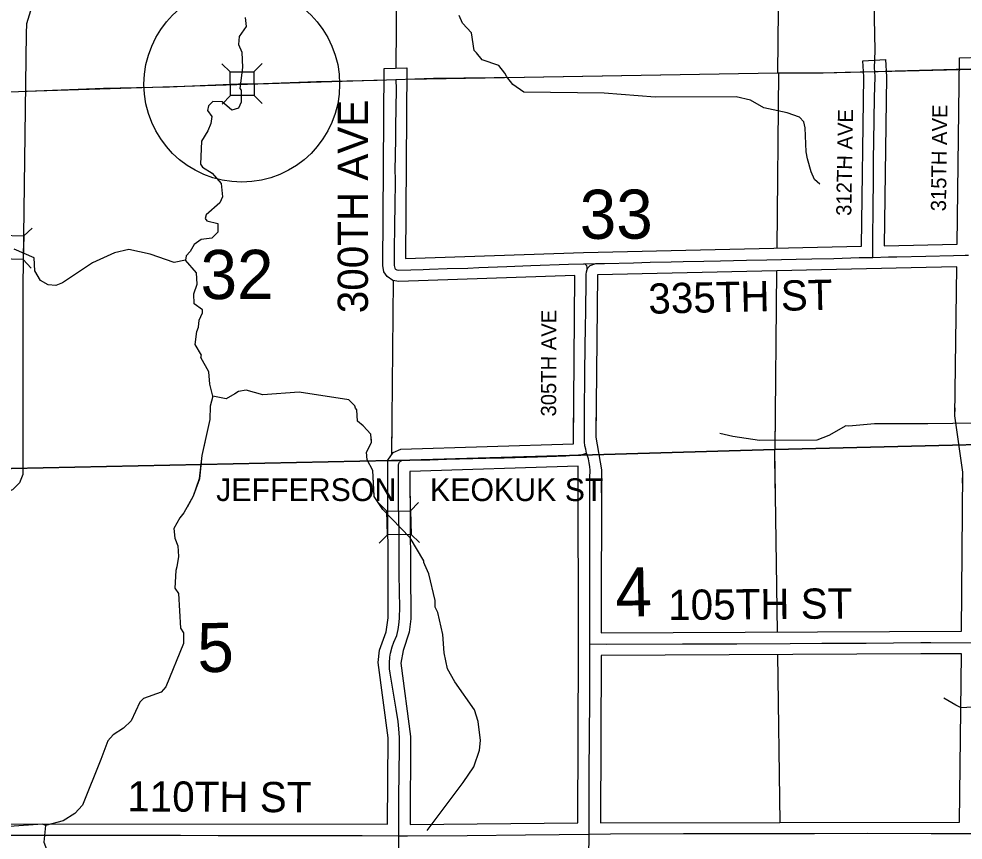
# Model space of a CAD drawing. Extents: x 10133 to 81668, y 7924 to 11018.
# Drawn here: x 11451.5 to 11826.5, y 8891.2 to 9217.2 of the extents above; entities that cross this region are included whole.
import ezdxf

# ---------------------------------------------------------------- set-up
doc = ezdxf.new("R2010")
doc.units = 0
for name, color, linetype in [('SheetBorder', 7, 'Continuous'), ('tdCoCityStreetMajor', 7, 'Continuous'), ('tdCoCityStreetMinor', 7, 'Continuous'), ('tdCoHydroRiver', 7, 'Continuous'), ('tdCoPriNonDiv', 7, 'Continuous'), ('tdCoRROwnerTxt', 7, 'Continuous'), ('tdCoShieldCoRte', 7, 'Continuous'), ('tdCoShieldCoRteHrd', 7, 'Continuous'), ('tdCoShieldStRte', 7, 'Continuous'), ('tdCoStrucNonDivPri', 7, 'Continuous'), ('tdCoStrucSec', 7, 'Continuous'), ('tdCoSurfGravel', 7, 'Continuous'), ('tdCoTwpBndryShd', 7, 'Continuous'), ('tdCoTwpNameTxt', 7, 'Continuous'), ('tdCoTwpRngTxt', 7, 'Continuous')]:
    doc.layers.add(name, color=color, linetype=linetype)

msp = doc.modelspace()

# ---------------------------------------------------------------- linework, layer by layer
at = {"layer": 'SheetBorder'}
msp.add_circle((11540.08, 9191.25), 38.85, dxfattribs=at)
at = {"layer": 'tdCoCityStreetMajor'}
for points in [[(11678.28, 8969.06), (11684.98, 8969.01), (11715.05, 8969.16), (11736.66, 8969.05), (11757.89, 8969.31), (11770.39, 8969.32)], [(11599.8, 8741.54), (11599.87, 8743), (11599.9, 8755.47), (11600.09, 8765.6), (11600.31, 8788.83), (11600.53, 8804.37), (11600.61, 8811.43), (11600.64, 8813.69), (11600.83, 8814.84), (11601.09, 8816.13), (11601.53, 8817.54), (11601.94, 8819.05), (11602.05, 8822.24), (11602.12, 8834.66), (11602.23, 8848.06), (11602.23, 8861.26), (11602.45, 8883.97), (11602.45, 8892.95)]]:
    msp.add_lwpolyline(points, dxfattribs=at)
at = {"layer": 'tdCoCityStreetMinor'}
for points in [[(11790.62, 9122.52), (11790.65, 9123.5), (11790.67, 9124.51), (11790.7, 9129.91), (11790.8, 9142.04), (11790.87, 9153.63), (11790.99, 9161.65), (11791.04, 9168.45), (11791.29, 9185.96), (11791.58, 9194.19), (11791.46, 9196.37)], [(11601.22, 9193.13), (11601.32, 9189.36), (11601.06, 9174.4), (11601.06, 9170.65), (11600.96, 9161.99), (11600.87, 9158.17), (11600.94, 9152.7), (11600.87, 9143.18), (11600.69, 9135.53), (11600.64, 9125), (11600.62, 9119.26), (11600.79, 9118.29), (11601.03, 9117.97), (11601.14, 9117.83), (11601.61, 9117.6), (11602.3, 9117.48), (11612.14, 9117.75), (11614.58, 9117.83), (11621.56, 9118.05), (11629.89, 9118.27), (11634.18, 9118.47), (11645.28, 9118.89), (11654.8, 9119.26), (11669.87, 9119.82), (11675.93, 9120)], [(11790.62, 9122.52), (11796.94, 9122.68), (11800.2, 9122.78), (11811.71, 9123.03), (11822.69, 9123.25), (11827.28, 9123.35), (11828.65, 9123.44)], [(11675.93, 9120), (11680.65, 9120.05)], [(11677.27, 9117.7), (11677.22, 9118.67), (11677.09, 9119.11), (11676.9, 9119.33), (11676.6, 9119.63), (11675.93, 9120)], [(11677.27, 9117.7), (11677.66, 9118.49), (11678.48, 9119.28), (11680.65, 9120.05)], [(11680.65, 9120.05), (11684.15, 9120.09), (11695.56, 9120.34), (11702.25, 9120.59), (11710.53, 9120.74), (11715.34, 9120.83), (11723.58, 9121.01), (11730.19, 9121.13), (11740.49, 9121.38), (11748.51, 9121.55), (11760.17, 9121.82), (11766.39, 9121.94), (11775.22, 9122.14), (11785.3, 9122.41), (11790.16, 9122.51), (11790.62, 9122.52)], [(11677.02, 9044.74), (11676.63, 9046.36), (11676.33, 9047.74), (11676.23, 9049.27), (11676.11, 9051.05), (11676.13, 9054.92), (11676.23, 9062.05), (11676.36, 9075.26), (11676.45, 9088.56), (11676.6, 9093.19), (11676.7, 9102.76), (11676.8, 9111.86), (11676.82, 9115.68), (11677, 9116.79), (11677.27, 9117.7)], [(11677.02, 9044.74), (11676.63, 9046.36), (11676.33, 9047.74), (11676.23, 9049.27), (11676.11, 9051.05), (11676.13, 9054.92), (11676.19, 9058.89)], [(11602.45, 8892.95), (11602.45, 8894.37), (11602.42, 8908.28), (11602.64, 8927.62), (11602.64, 8931.99), (11602.42, 8935.32), (11602.27, 8936.82), (11602.12, 8938.31), (11601.38, 8943.2), (11600.27, 8949.48), (11598.98, 8957.47), (11598.79, 8959.25), (11598.72, 8961.58), (11598.87, 8963.84), (11599.16, 8965.43), (11599.79, 8967.87), (11600.49, 8969.72), (11601.64, 8972.46), (11602.23, 8974.79), (11602.49, 8976.67), (11602.68, 8979.19), (11602.7, 8979.72), (11602.86, 8983.41), (11602.6, 8996.61), (11602.57, 9013.37), (11602.34, 9024.58), (11602.3, 9035.07), (11602.3, 9035.54), (11602.3, 9040.07), (11602.37, 9040.69), (11602.67, 9041.28), (11603.23, 9041.79), (11603.24, 9041.8), (11603.68, 9041.96), (11603.73, 9041.97), (11614.75, 9042.22), (11621.31, 9042.42), (11636.97, 9042.84), (11644.32, 9043.01), (11657.49, 9043.4), (11665.09, 9043.58), (11668.73, 9043.72), (11671.74, 9043.99), (11673.81, 9044.12), (11675.17, 9044.27), (11676.21, 9044.51), (11677.02, 9044.74)], [(11602.33, 9026.92), (11602.3, 9035.07), (11602.3, 9035.53), (11602.3, 9040.07), (11602.37, 9040.69), (11602.67, 9041.28), (11603.23, 9041.79), (11603.24, 9041.8), (11603.68, 9041.95), (11603.73, 9041.97), (11614.75, 9042.22), (11621.31, 9042.42), (11636.97, 9042.83), (11644.32, 9043.01), (11657.49, 9043.4), (11665.09, 9043.57), (11668.73, 9043.72), (11671.74, 9043.99), (11673.81, 9044.12), (11675.17, 9044.26), (11676.21, 9044.51), (11677.02, 9044.74)], [(11677.96, 8893.57), (11677.96, 8903.69), (11678.03, 8919.82), (11678.11, 8930.69), (11678.22, 8948.93), (11678.22, 8955.96), (11678.29, 8966.72), (11678.28, 8969.06), (11678.25, 8978.93), (11678.29, 8995.02), (11678.22, 9006.12), (11678.25, 9022.1), (11678.3, 9035.09), (11678.35, 9037.98), (11678.23, 9039.53), (11678.03, 9041.01), (11677.69, 9042.59), (11677.17, 9044.14), (11677.02, 9044.74)], [(11678.28, 9028.95), (11678.3, 9035.09), (11678.35, 9037.98), (11678.23, 9039.53), (11678.03, 9041.01), (11677.69, 9042.59), (11677.17, 9044.14), (11677.02, 9044.74)], [(11770.39, 8969.32), (11788, 8969.34), (11809.75, 8969.68), (11813.71, 8969.68), (11830.35, 8969.55)], [(11412.41, 8893.16), (11421.42, 8893.13), (11452.49, 8893.17), (11490, 8893.17), (11515.67, 8893.17), (11530.73, 8893.06), (11548, 8892.98), (11571.01, 8893.06), (11587.84, 8892.98), (11602.45, 8892.95)], [(11602.45, 8892.95), (11605.82, 8892.95), (11629.57, 8893.09), (11652.69, 8893.35), (11666.15, 8893.46), (11677.96, 8893.57)], [(11676.69, 8741.59), (11676.66, 8745.59), (11676.7, 8757.06), (11677.03, 8775.48), (11677.14, 8786.1), (11677.37, 8801.23), (11677.4, 8811.81), (11677.59, 8828.64), (11677.62, 8839.96), (11677.74, 8852.24), (11677.74, 8863.63), (11677.81, 8879.02), (11677.96, 8892.33), (11677.96, 8893.57)], [(11677.96, 8893.57), (11686.46, 8893.65), (11715.42, 8893.76), (11735.36, 8893.83), (11751.89, 8893.83), (11767.47, 8893.83), (11788.41, 8893.95), (11813.85, 8893.83), (11829.54, 8893.79)]]:
    msp.add_lwpolyline(points, dxfattribs=at)
at = {"layer": 'tdCoHydroRiver'}
for points in [[(11541.44, 9217.78), (11541.74, 9214.24), (11538.97, 9210.16), (11538.78, 9207.08), (11540.02, 9204.03), (11540.36, 9197.87), (11539.31, 9189.57), (11539.8, 9188.87), (11539.88, 9184.13), (11538.73, 9181.75), (11536.14, 9180.99), (11532.3, 9184.24), (11528.51, 9184.42), (11526.88, 9182.73), (11526.43, 9180.83), (11528.13, 9178.49), (11527.71, 9175.64), (11526.57, 9172.78), (11524.03, 9168.71), (11523.72, 9159.47), (11524.45, 9158.3), (11528.27, 9156), (11531.89, 9151.79), (11532.46, 9146.59), (11531.31, 9144.21), (11525.95, 9139.38), (11525.5, 9137.95), (11526.22, 9137.02), (11530.5, 9135.91), (11530.56, 9132.59), (11528.23, 9130.18), (11523.98, 9129.64), (11521.17, 9127.7), (11519.56, 9124.83), (11517.93, 9123.14), (11517.72, 9121.48)], [(11769.64, 9151.53), (11767.48, 9153.38), (11766.24, 9156.44), (11764.73, 9161.62), (11764.21, 9164.46), (11763.82, 9173.92), (11763.3, 9176.28), (11761.61, 9178.15), (11756.61, 9179.96), (11747.34, 9181.93), (11742.08, 9184.92), (11736.38, 9186.25), (11704.17, 9186.18), (11684.02, 9187.74), (11652.05, 9188.15), (11647.74, 9191.15), (11645.32, 9194.19), (11644.58, 9195.6), (11642.16, 9198.64), (11635.5, 9200.89), (11633.32, 9203.7), (11632.35, 9204.63), (11631.29, 9211.71), (11627.67, 9215.44), (11626.44, 9218.5)], [(11517.72, 9121.48), (11513.24, 9120.46), (11503.71, 9123.85), (11495.16, 9125.6), (11489.5, 9124.32), (11480.8, 9120.39), (11468.86, 9112.37), (11466.27, 9111.38), (11463.19, 9111.57), (11460.08, 9113.41), (11457.89, 9117.16), (11457.56, 9122.37), (11449.69, 9125.79)], [(11528.58, 9067.44), (11527.31, 9072.15), (11526.99, 9077.12), (11523.82, 9082.75), (11524.04, 9083.7), (11521.6, 9087.92), (11522.22, 9093.14), (11522.91, 9094.81), (11523.1, 9097.66), (11524.47, 9100.52), (11524.45, 9101.71), (11521.1, 9104.02), (11521.03, 9108.04), (11522.38, 9111.85), (11522.07, 9116.35), (11517.72, 9121.48)], [(11528.58, 9067.44), (11527.46, 9063.4), (11527.31, 9058.18), (11524.24, 9043.92), (11523.21, 9034.67), (11520.72, 9027.76), (11518.34, 9023.43)], [(11592.69, 9027.83), (11592.06, 9037.96), (11589.86, 9042.18), (11589.57, 9045.26), (11591.63, 9049.08), (11591.34, 9052.39), (11588.21, 9055.65), (11586.05, 9057.51), (11585.73, 9062.01), (11585.25, 9062.71), (11585, 9063.65), (11582.59, 9065.98), (11562.89, 9068.96), (11548.46, 9068.01), (11541.8, 9069.79), (11538.73, 9069.27), (11537.32, 9068.3), (11533.8, 9066.34), (11528.58, 9067.44)], [(11893.46, 9035.42), (11889.44, 9038.85), (11883.23, 9041.58), (11870.17, 9043.47), (11865.88, 9045.05), (11863.45, 9048.8), (11858.37, 9053.35), (11852.86, 9056.01), (11842.4, 9056.88), (11812.5, 9056.44), (11791.37, 9056.49), (11781.18, 9055.46)], [(11781.18, 9055.46), (11779.99, 9055.66), (11773.15, 9051.85), (11768.43, 9050.01), (11745.6, 9049.87), (11735.11, 9051.37), (11729.86, 9052.59)], [(11525.37, 9049.2), (11524.23, 9043.92), (11523.2, 9034.67), (11520.71, 9027.76), (11517.04, 9021.07), (11515.41, 9019.15), (11513.12, 9014.85), (11513.42, 9011.06), (11514.65, 9008.01), (11514.96, 9003.75), (11514.32, 8999.71), (11513.87, 8998.28), (11513.51, 8991.17), (11514.97, 8989.07), (11515.67, 8975.35), (11516.89, 8973.47), (11516.96, 8969.21), (11509.91, 8952.04), (11508.05, 8949.88), (11500.99, 8947.39), (11499.59, 8945.95), (11496.16, 8938.55), (11493.13, 8935.66), (11488.92, 8932.98), (11486.83, 8930.58), (11484.11, 8923.19), (11476.83, 8905.07), (11473.81, 8901.71), (11469.13, 8898.79), (11462.05, 8897.01)], [(11613.63, 8895.06), (11628, 8914.01), (11632.15, 8920.23), (11634.41, 8926.9), (11634.82, 8930.7), (11633.98, 8938.26), (11632.48, 8942.97), (11624.72, 8953.97), (11621.79, 8959.13), (11620.5, 8965.5), (11619.9, 8972.83), (11617.86, 8981.56), (11616.88, 8983.68), (11616.84, 8986.28), (11614.29, 8996.89), (11612.81, 9000.42), (11612.32, 9001.36), (11612.31, 9002.07), (11606.95, 9011.21), (11596.1, 9022.4), (11592.7, 9027.55), (11592.05, 9037.96), (11589.85, 9042.18), (11589.56, 9045.26), (11591.63, 9049.08), (11591.52, 9050.32)], [(11898.87, 9027.66), (11897.46, 9027.16), (11894.21, 9023.55), (11891.25, 9017.33), (11889.04, 9008.53), (11883.39, 8993.51), (11875.66, 8975.85), (11874.99, 8973.94), (11870.42, 8964.86), (11866.03, 8958.62), (11859.76, 8952.11), (11850.62, 8946.97), (11841.19, 8944.67), (11825.81, 8943.68), (11823.66, 8944.82), (11818.87, 8947.58)], [(11462.05, 8897.01), (11461.45, 8890.37), (11462.45, 8887.55), (11465.59, 8884.05), (11466.09, 8882.16), (11465, 8876.7), (11465.07, 8872.44), (11465.12, 8869.6), (11466.35, 8866.77), (11467.11, 8863.71), (11467.36, 8862.77), (11467.97, 8854.96), (11467.54, 8852.11), (11465.98, 8846.17), (11465.55, 8844.03), (11463.98, 8838.79), (11461.46, 8833.54), (11461.34, 8826.91), (11462.07, 8825.26), (11462.04, 8813.19), (11461.62, 8810.1), (11460.71, 8807.72), (11454.75, 8796.01), (11436.23, 8771.08)], [(11462.05, 8897.01), (11460.86, 8897.47), (11447.85, 8896.54)]]:
    msp.add_lwpolyline(points, dxfattribs=at)
at = {"layer": 'tdCoPriNonDiv'}
for points in [[(11456.75, 9222.11), (11454.63, 9215.25), (11454.45, 9211.45), (11453.15, 9111.11), (11453.09, 9036.32), (11451.81, 9032.96), (11448.95, 9030.28), (11446.21, 9029.19), (11438.5, 9028.81), (11437.64, 9028.09), (11437.23, 9026.57), (11436.7, 9023.29)], [(11598.09, 9026.84), (11598.06, 9041.98), (11600.2, 9045.12), (11603.28, 9046.45), (11671.77, 9048.5), (11672.32, 9115.39), (11602.42, 9112.98), (11600.05, 9113.38), (11597.75, 9114.87), (11596.54, 9116.84), (11596.12, 9119.28), (11596.61, 9197.51), (11605.6, 9197.74), (11605.13, 9122.06), (11675.8, 9124.49), (11786.19, 9126.93), (11787.08, 9194.15), (11786.71, 9200.6), (11795.69, 9201.12), (11796.08, 9194.24), (11795.18, 9127.14), (11824.18, 9127.78), (11825.03, 9201.8), (11834.02, 9202)], [(11826.33, 9032.9), (11826.36, 9037.2), (11823.28, 9059.57), (11824.09, 9118.78), (11811.81, 9118.53), (11681.35, 9115.53), (11680.61, 9051.19), (11682.85, 9038.12), (11682.84, 9029.07)], [(11825.87, 8974.09), (11826.36, 9037.2), (11823.28, 9059.57), (11823.33, 9062.81)], [(11597.95, 8897.46), (11598.14, 8931.84), (11594.22, 8961.66), (11594.81, 8966.55), (11597.36, 8973.89), (11598.19, 8979.45), (11598.06, 9041.98), (11600.2, 9045.12), (11603.28, 9046.45), (11671.77, 9048.5), (11671.86, 9058.77)], [(11680.7, 9059.01), (11680.61, 9051.19), (11682.85, 9038.12), (11682.77, 8973.53), (11825.87, 8974.09)], [(11453.1, 9053.84), (11453.09, 9036.32), (11451.81, 9032.96), (11448.95, 9030.28), (11446.21, 9029.19), (11438.5, 9028.81), (11437.64, 9028.09), (11437.23, 9026.57), (11427.82, 8968.37), (11417.21, 8897.64), (11597.95, 8897.46)], [(11606.94, 8897.45), (11673.46, 8898.03), (11673.79, 8966.73), (11673.68, 9039.6), (11606.8, 9037.54), (11607.17, 8978.99), (11606.59, 8973.68), (11604.09, 8966.5), (11603.22, 8961.5), (11607.13, 8932.29), (11606.94, 8897.45)], [(11673.7, 9028.83), (11673.68, 9039.6), (11606.8, 9037.54), (11606.86, 9027.04)], [(11682.46, 8898.11), (11825.07, 8898.3), (11825.85, 8965.09), (11809.79, 8965.18), (11682.77, 8964.53), (11682.46, 8898.11)]]:
    msp.add_lwpolyline(points, dxfattribs=at)
at = {"layer": 'tdCoShieldCoRte'}
for points in [[(11440.93, 9134.74), (11444.14, 9131.32), (11453.52, 9131.03)], [(11456.87, 9134.17), (11453.52, 9131.03), (11453.23, 9121.65)], [(11456.45, 9118.23), (11453.23, 9121.65), (11443.85, 9121.94)], [(11594.32, 9025.02), (11597.71, 9021.77), (11607.09, 9021.96)], [(11610.27, 9025.27), (11607.09, 9021.96), (11607.27, 9012.57)], [(11594.64, 9009.01), (11597.89, 9012.39), (11597.71, 9021.77)], [(11610.66, 9009.32), (11607.27, 9012.57), (11597.89, 9012.39)]]:
    msp.add_lwpolyline(points, dxfattribs=at)
at = {"layer": 'tdCoShieldCoRteHrd'}
for points in [[(11681.85, 9044.24), (11751.71, 9046.27), (11824.76, 9048.05)], [(11681.86, 9044.24), (11751.72, 9046.27), (11824.77, 9048.05)], [(11453.11, 9038.84), (11598.04, 9041.85)], [(11453.11, 9038.84), (11598.05, 9041.85)]]:
    msp.add_lwpolyline(points, dxfattribs=at)
at = {"layer": 'tdCoStrucNonDivPri'}
for points in [[(11601.88, 9278.86), (11601.26, 9197.63)], [(11605.72, 9193.21), (11752.84, 9195.81)], [(11753.24, 9195.79), (11752.53, 9126.19)], [(11454.25, 9188.47), (11596.73, 9192.99)], [(11752.44, 9117.17), (11751.72, 9046.27)], [(11599.61, 9044.5), (11600.36, 9113.33)], [(11751.86, 9060.91), (11751.71, 9046.27)], [(11599.6, 9044.5), (11599.74, 9056.87)], [(11681.85, 9044.24), (11751.71, 9046.27)], [(11681.86, 9044.24), (11751.72, 9046.27)], [(11751.71, 9046.27), (11824.76, 9048.05)], [(11752.78, 8973.74), (11751.71, 9046.27)], [(11751.72, 9046.27), (11824.77, 9048.05)], [(11751.94, 9030.91), (11751.72, 9046.27)], [(11453.11, 9038.84), (11598.04, 9041.85)], [(11453.11, 9038.84), (11598.05, 9041.85)], [(11753.9, 8898.34), (11752.92, 8964.75)]]:
    msp.add_lwpolyline(points, dxfattribs=at)
at = {"layer": 'tdCoStrucSec'}
msp.add_lwpolyline([(11448.12, 9188.29), (11485.13, 9189.73), (11511.4, 9190.16), (11538.73, 9191.44), (11548.63, 9191.5), (11569.79, 9192.29), (11593.85, 9192.84), (11616.2, 9193.63), (11652.37, 9194.07), (11752.87, 9195.82), (11770.92, 9195.82), (11885.25, 9198.58), (12034.74, 9202.48), (12056.79, 9202.66), (12070.8, 9202.78), (12088.36, 9202.53), (12109.96, 9201.59), (12163.18, 9200.16), (12264.21, 9197.78)], dxfattribs=at)
at = {"layer": 'tdCoSurfGravel'}
msp.add_lwpolyline([(11753.46, 9257.83), (11752.84, 9195.79), (11756.05, 9195.78), (11760.21, 9195.72), (11770.92, 9195.82), (11779.7, 9196.02), (11791.46, 9196.37), (11799.57, 9196.61), (11823.82, 9197.18), (11826.76, 9197.29), (11829.62, 9197.4), (11832.17, 9197.5), (11841.4, 9197.6), (11844.16, 9197.65), (11857.97, 9197.94), (11879.42, 9198.53), (11885.24, 9198.58), (11896.44, 9198.93), (11905.29, 9199.19), (11905.17, 9206.37), (11905.22, 9227.48)], dxfattribs=at)
at = {"layer": 'tdCoTwpBndryShd'}
msp.add_lwpolyline([(11791.46, 9196.37), (11791.39, 9197.64), (11791.58, 9204.6), (11791.39, 9217.45), (11791.31, 9226.18), (11791.26, 9232.76), (11791.22, 9237.48), (11791.18, 9239.37), (11791.11, 9242.5), (11791.04, 9245.99), (11790.99, 9248.2), (11790.98, 9253.24), (11790.97, 9260.14), (11790.99, 9261.84), (11790.99, 9262.38)], dxfattribs=at)
at = {"layer": 'tdCoTwpNameTxt'}
for points in [[(12204.65, 9594.91), (12205.81, 9506.76), (12207.26, 9355.85), (12207.65, 9199.23), (12206.71, 9053.29), (12058.44, 9052.45), (12055.44, 9052.43), (11906.7, 9050.03), (11903.62, 9049.96), (11751.72, 9046.27), (11602.3, 9041.92), (11599.58, 9041.89), (11448.66, 9038.75), (11287.47, 9032.68), (11137.48, 9029.42), (10987.91, 9025.85), (10954.88, 9025.06)], [(10954.88, 9025.06), (10987.91, 9025.85), (11137.48, 9029.42), (11287.46, 9032.68), (11448.65, 9038.75), (11599.58, 9041.89), (11602.29, 9041.92), (11751.71, 9046.27), (11903.62, 9049.96), (11906.69, 9050.03), (12055.44, 9052.43), (12058.43, 9052.45), (12206.7, 9053.29), (12354.1, 9050.96), (12408.9, 9050.4)]]:
    msp.add_lwpolyline(points, dxfattribs=at)
at = {"layer": 'tdCoTwpRngTxt'}
for points in [[(11532.15, 9199.42), (11535.48, 9196.12), (11544.87, 9196.17)], [(11548.17, 9199.5), (11544.87, 9196.17), (11544.92, 9186.78)], [(11532.23, 9183.4), (11535.53, 9186.74), (11535.48, 9196.12)], [(11548.18, 9183.55), (11544.92, 9186.78), (11535.53, 9186.74)]]:
    msp.add_lwpolyline(points, dxfattribs=at)

# ---------------------------------------------------------------- texts
at = {"layer": 'tdCoRROwnerTxt'}
for s, rotation, p in [('33', 0.229, (11674.31, 9129.85)), ('32', 0.2282, (11523.73, 9105.94)), ('4', 1.1444, (11688.61, 8979.78)), ('5', 1.1436, (11522.56, 8957.79))]:
    msp.add_text(s, height=19.5, rotation=rotation, dxfattribs=at).set_placement(p)
at = {"layer": 'tdCoShieldStRte'}
for s, height, rotation, p in [('300TH AVE', 12, 90, (11590.16, 9100.36)), ('312TH AVE', 6, 88.9995, (11782.1, 9138.97)), ('315TH AVE', 6, 89.1846, (11819.69, 9140.79)), ('335TH ST', 12, 1.2893, (11701.64, 9100.12)), ('305TH AVE', 6, 89.8235, (11664.88, 9059.34)), ('105TH ST', 12, 0.5101, (11709.45, 8978.55)), ('110TH ST', 12, 359.6797, (11494.55, 8902.61))]:
    msp.add_text(s, height=height, rotation=rotation, dxfattribs=at).set_placement(p)
msp.add_text('JEFFERSON    KEOKUK ST', height=9, dxfattribs=at).set_placement((11529.89, 9025.79))

doc.saveas('drawing.dxf')
